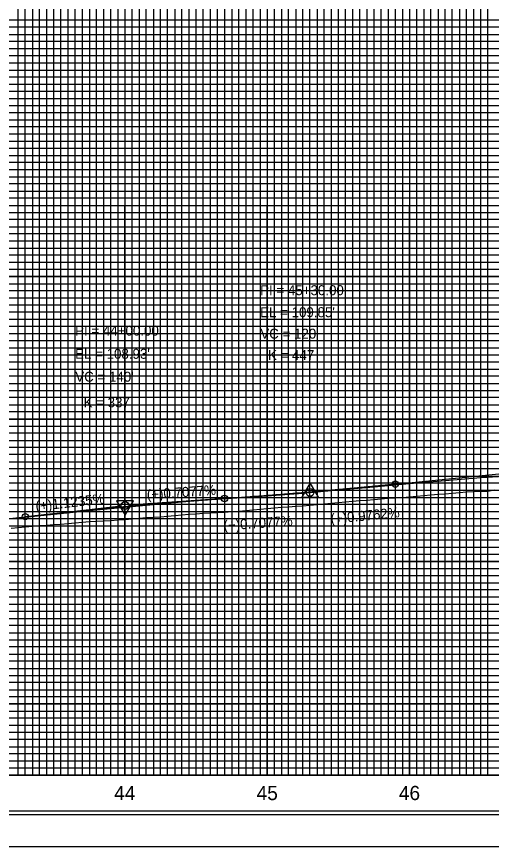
# Model space of a CAD drawing. Extents: x 2345490 to 2436403, y 465165 to 573888.
# Drawn here: x 2385091 to 2385424, y 515088 to 515670 of the extents above; entities that cross this region are included whole.
import ezdxf

# ---------------------------------------------------------------- set-up
doc = ezdxf.new("R2010")
doc.units = 0
for name, color, linetype in [('Old_Level_1', 7, 'Continuous'), ('Old_Level_18', 7, 'Continuous'), ('Old_Level_2', 7, 'Continuous'), ('Old_Level_41', 7, 'Continuous'), ('Old_Level_42', 7, 'Continuous'), ('Old_Level_43', 7, 'Continuous'), ('Old_Level_50', 7, 'Continuous'), ('Old_Level_51', 7, 'Continuous'), ('Old_Level_57', 7, 'Continuous'), ('Old_Level_61', 7, 'Continuous'), ('Old_Level_62', 7, 'Continuous'), ('Old_Level_63', 7, 'Continuous')]:
    doc.layers.add(name, color=color, linetype=linetype)

msp = doc.modelspace()

# ---------------------------------------------------------------- linework, layer by layer
at = {"layer": 'Old_Level_1'}
for points in [[(2385266.799, 515324.72275), (2385271.799, 515325.179), (2385276.799, 515325.58875), (2385281.799, 515325.93025), (2385286.799, 515326.27175), (2385291.799, 515326.662), (2385296.799, 515327.1245), (2385301.799, 515327.5825), (2385306.799, 515328.0385), (2385311.799, 515328.4945), (2385316.799, 515328.90475), (2385321.799, 515329.3655), (2385326.799, 515329.828), (2385331.799, 515330.2905), (2385336.799, 515330.61575), (2385341.799, 515330.98925), (2385346.799, 515331.45175), (2385351.799, 515331.91425), (2385356.799, 515332.30325), (2385361.799, 515332.5325), (2385366.799, 515332.9715), (2385371.799, 515333.41175), (2385376.799, 515333.852), (2385381.799, 515334.2775), (2385386.799, 515334.6985), (2385391.799, 515335.11925), (2385396.799, 515335.54025), (2385401.799, 515335.961), (2385406.799, 515336.382), (2385411.799, 515336.64275), (2385416.799, 515336.78), (2385421.799, 515336.9175), (2385426.799, 515337.8635)], [(2385086.799, 515310.91325), (2385091.799, 515311.27425), (2385096.799, 515311.77975), (2385101.799, 515312.285), (2385106.799, 515312.7905), (2385111.799, 515313.12575), (2385116.799, 515313.418), (2385121.799, 515313.7105), (2385126.799, 515314.17125), (2385131.799, 515314.6765), (2385136.799, 515315.182), (2385141.799, 515315.51675), (2385146.799, 515315.80925), (2385151.799, 515316.1015), (2385156.799, 515316.3905), (2385161.799, 515316.6785), (2385166.799, 515317.07925), (2385171.799, 515317.5565), (2385176.799, 515318.03375), (2385181.799, 515318.368), (2385186.799, 515318.65625), (2385191.799, 515318.9445), (2385196.799, 515319.3745), (2385201.799, 515319.85175), (2385206.799, 515320.32875), (2385211.799, 515320.70325), (2385216.799, 515321.045), (2385221.799, 515321.3505), (2385226.799, 515321.639), (2385231.799, 515321.9275), (2385236.799, 515322.25175), (2385241.799, 515322.5935), (2385246.799, 515322.93525), (2385251.799, 515323.35425), (2385256.799, 515323.8105), (2385261.799, 515324.2665), (2385266.799, 515324.72275)]]:
    msp.add_lwpolyline(points, dxfattribs=at)
at = {"layer": 'Old_Level_18'}
msp.add_lwpolyline([(2386016.79875, 516162.5265), (2384516.79875, 516162.5265), (2384516.79875, 515112.5265), (2386016.79875, 515112.5265)], close=True, dxfattribs=at)
at = {"layer": 'Old_Level_2'}
for p, q in [((2385356.799, 515341.88375), (2385431.799, 515349.20525)), ((2385356.799, 515341.88375), (2385299.536, 515336.29375)), ((2385236.799, 515331.7805), (2385294.056, 515335.8325)), ((2385096.799, 515318.962), (2385164.06625, 515326.5195)), ((2385236.799, 515331.7805), (2385169.54225, 515327.02075)), ((2385076.799, 515316.71475), (2385096.799, 515318.962))]:
    msp.add_line(p, q, dxfattribs=at)
for points in [[(2385290.99325, 515332.5755), (2385302.73575, 515332.5755), (2385296.86475, 515342.70125)], [(2385172.72475, 515330.111), (2385160.98225, 515330.0965), (2385166.86575, 515319.97825)]]:
    msp.add_lwpolyline(points, close=True, dxfattribs=at)
for centre, radius in [((2385356.799, 515341.88375), 2.25), ((2385296.799, 515336.0265), 2.75), ((2385236.799, 515331.7805), 2.25), ((2385166.799, 515326.8265), 2.75), ((2385166.799, 515326.8265), 2.75), ((2385096.799, 515318.962), 2.25)]:
    msp.add_circle(centre, radius, dxfattribs=at)
for points in [[(2385236.799, 515331.7805), (2385239.199, 515331.951), (2385241.599, 515332.12275), (2385243.999, 515332.29575), (2385246.399, 515332.47025), (2385248.799, 515332.64575), (2385251.199, 515332.82275), (2385253.599, 515333.001), (2385255.999, 515333.1805), (2385258.399, 515333.36125), (2385260.799, 515333.54325), (2385263.199, 515333.72675), (2385265.599, 515333.9115), (2385267.999, 515334.09725), (2385270.399, 515334.2845), (2385272.799, 515334.47325), (2385275.199, 515334.663), (2385277.599, 515334.854), (2385279.999, 515335.0465), (2385282.399, 515335.24025), (2385284.799, 515335.43525), (2385287.199, 515335.6315), (2385289.599, 515335.829), (2385291.999, 515336.02775), (2385294.399, 515336.228), (2385296.799, 515336.42925), (2385299.199, 515336.632), (2385301.599, 515336.836), (2385303.999, 515337.04125), (2385306.399, 515337.248), (2385308.799, 515337.45575), (2385311.199, 515337.665), (2385313.599, 515337.8755), (2385315.999, 515338.08725), (2385318.399, 515338.30025), (2385320.799, 515338.5145), (2385323.199, 515338.73), (2385325.599, 515338.947), (2385327.999, 515339.16525), (2385330.399, 515339.3845), (2385332.799, 515339.60525), (2385335.199, 515339.8275), (2385337.599, 515340.05075), (2385339.999, 515340.27525), (2385342.399, 515340.50125), (2385344.799, 515340.7285), (2385347.199, 515340.957), (2385349.599, 515341.18675), (2385351.999, 515341.41775), (2385354.399, 515341.65025), (2385356.799, 515341.88375)], [(2385096.799, 515318.962), (2385099.599, 515319.27525), (2385102.399, 515319.5865), (2385105.199, 515319.89525), (2385107.999, 515320.20175), (2385110.799, 515320.50575), (2385113.599, 515320.8075), (2385116.399, 515321.107), (2385119.199, 515321.404), (2385121.999, 515321.699), (2385124.799, 515321.99125), (2385127.599, 515322.2815), (2385130.399, 515322.56925), (2385133.199, 515322.85475), (2385135.999, 515323.138), (2385138.799, 515323.41875), (2385141.599, 515323.69725), (2385144.399, 515323.9735), (2385147.199, 515324.24725), (2385149.999, 515324.51875), (2385152.799, 515324.788), (2385155.599, 515325.05475), (2385158.399, 515325.31925), (2385161.199, 515325.5815), (2385163.999, 515325.84125), (2385166.799, 515326.099), (2385169.599, 515326.354), (2385172.399, 515326.607), (2385175.199, 515326.8575), (2385177.999, 515327.10575), (2385180.799, 515327.35175), (2385183.599, 515327.59525), (2385186.399, 515327.8365), (2385189.199, 515328.07525), (2385191.999, 515328.312), (2385194.799, 515328.54625), (2385197.599, 515328.778), (2385200.399, 515329.00775), (2385203.199, 515329.235), (2385205.999, 515329.46), (2385208.799, 515329.6825), (2385211.599, 515329.90275), (2385214.399, 515330.12075), (2385217.199, 515330.33625), (2385219.999, 515330.54975), (2385222.799, 515330.7605), (2385225.599, 515330.96925), (2385228.399, 515331.1755), (2385231.199, 515331.3795), (2385233.999, 515331.58125), (2385236.799, 515331.7805)]]:
    msp.add_spline(points, degree=3, dxfattribs=at)
at = {"layer": 'Old_Level_41'}
msp.add_line((2386016.79875, 515137.5265), (2384516.79875, 515137.5265), dxfattribs=at)
for points in [[(2385041.79875, 515137.5265), (2385091.79875, 515137.5265), (2385091.79875, 516162.5265)], [(2385066.79875, 515137.5265), (2385116.79875, 515137.5265), (2385116.79875, 516162.5265)], [(2385141.79875, 516162.5265), (2385141.79875, 515137.5265), (2385191.79875, 515137.5265), (2385191.79875, 516162.5265)], [(2385166.79875, 516162.5265), (2385166.79875, 515137.5265), (2385216.79875, 515137.5265), (2385216.79875, 516162.5265)], [(2385241.79875, 516162.5265), (2385241.79875, 515137.5265), (2385291.79875, 515137.5265), (2385291.79875, 516162.5265)], [(2385266.79875, 516162.5265), (2385266.79875, 515137.5265), (2385316.79875, 515137.5265), (2385316.79875, 516162.5265)], [(2385341.79875, 516162.5265), (2385341.79875, 515137.5265), (2385391.79875, 515137.5265), (2385391.79875, 516162.5265)], [(2385366.79875, 516162.5265), (2385366.79875, 515137.5265), (2385416.79875, 515137.5265), (2385416.79875, 516162.5265)], [(2386016.79875, 515662.5265), (2384516.79875, 515662.5265), (2384516.79875, 515612.5265), (2386016.79875, 515612.5265)], [(2386016.79875, 515562.5265), (2384516.79875, 515562.5265), (2384516.79875, 515512.5265), (2386016.79875, 515512.5265)], [(2386016.79875, 515487.5265), (2384516.79875, 515487.5265), (2384516.79875, 515537.5265), (2386016.79875, 515537.5265)], [(2386016.79875, 515462.5265), (2384516.79875, 515462.5265), (2384516.79875, 515412.5265), (2386016.79875, 515412.5265)], [(2386016.79875, 515387.5265), (2384516.79875, 515387.5265), (2384516.79875, 515437.5265), (2386016.79875, 515437.5265)], [(2386016.79875, 515362.5265), (2384516.79875, 515362.5265), (2384516.79875, 515312.5265), (2386016.79875, 515312.5265)], [(2386016.79875, 515262.5265), (2384516.79875, 515262.5265), (2384516.79875, 515212.5265), (2386016.79875, 515212.5265)], [(2386016.79875, 515187.5265), (2384516.79875, 515187.5265), (2384516.79875, 515237.5265), (2386016.79875, 515237.5265)], [(2386016.79875, 515162.5265), (2384516.79875, 515162.5265)]]:
    msp.add_lwpolyline(points, dxfattribs=at)
at = {"layer": 'Old_Level_42'}
for points in [[(2386016.79875, 515587.5265), (2384516.79875, 515587.5265), (2384516.79875, 515637.5265), (2386016.79875, 515637.5265)], [(2386016.79875, 515287.5265), (2384516.79875, 515287.5265), (2384516.79875, 515337.5265), (2386016.79875, 515337.5265)]]:
    msp.add_lwpolyline(points, dxfattribs=at)
at = {"layer": 'Old_Level_43'}
for points in [[(2385096.79875, 515137.5265), (2385096.79875, 516162.5265)], [(2385101.79875, 516162.5265), (2385101.79875, 515137.5265), (2385106.79875, 515137.5265), (2385106.79875, 516162.5265)], [(2385111.79875, 516162.5265), (2385111.79875, 515137.5265), (2385121.79875, 515137.5265), (2385121.79875, 516162.5265)], [(2385126.79875, 516162.5265), (2385126.79875, 515137.5265), (2385126.79875, 515137.5265), (2385131.79875, 515137.5265), (2385131.79875, 516162.5265)], [(2385136.79875, 516162.5265), (2385136.79875, 515137.5265), (2385146.79875, 515137.5265), (2385146.79875, 516162.5265)], [(2385151.79875, 516162.5265), (2385151.79875, 515137.5265), (2385156.79875, 515137.5265), (2385156.79875, 516162.5265)], [(2385161.79875, 516162.5265), (2385161.79875, 515137.5265), (2385171.79875, 515137.5265), (2385171.79875, 516162.5265)], [(2385176.79875, 516162.5265), (2385176.79875, 515137.5265), (2385181.79875, 515137.5265), (2385181.79875, 516162.5265)], [(2385186.79875, 516162.5265), (2385186.79875, 515137.5265), (2385196.79875, 515137.5265), (2385196.79875, 516162.5265)], [(2385201.79875, 516162.5265), (2385201.79875, 515137.5265), (2385206.79875, 515137.5265), (2385206.79875, 516162.5265)], [(2385211.79875, 516162.5265), (2385211.79875, 515137.5265), (2385221.79875, 515137.5265), (2385221.79875, 516162.5265)], [(2385226.79875, 516162.5265), (2385226.79875, 515137.5265), (2385231.79875, 515137.5265), (2385231.79875, 516162.5265)], [(2385236.79875, 516162.5265), (2385236.79875, 515137.5265), (2385246.79875, 515137.5265), (2385246.79875, 516162.5265)], [(2385251.79875, 516162.5265), (2385251.79875, 515137.5265), (2385256.79875, 515137.5265), (2385256.79875, 516162.5265)], [(2385261.79875, 516162.5265), (2385261.79875, 515137.5265), (2385271.79875, 515137.5265), (2385271.79875, 516162.5265)], [(2385276.79875, 516162.5265), (2385276.79875, 515137.5265)], [(2385276.79875, 515137.5265), (2385281.79875, 515137.5265), (2385281.79875, 516161.9265)], [(2385286.79875, 516161.9265), (2385286.79875, 515137.5265), (2385296.79875, 515137.5265), (2385296.79875, 516162.5265)], [(2385301.79875, 516162.5265), (2385301.79875, 515137.5265), (2385306.79875, 515137.5265), (2385306.79875, 516162.5265)], [(2385311.79875, 516162.5265), (2385311.79875, 515137.5265), (2385321.79875, 515137.5265), (2385321.79875, 516162.5265)], [(2385326.79875, 516162.5265), (2385326.79875, 515137.5265), (2385331.79875, 515137.5265), (2385331.79875, 516162.5265)], [(2385336.79875, 516162.5265), (2385336.79875, 515137.5265), (2385346.79875, 515137.5265), (2385346.79875, 516162.5265)], [(2385351.79875, 516162.5265), (2385351.79875, 515137.5265), (2385356.79875, 515137.5265), (2385356.79875, 516162.5265)], [(2385361.79875, 516162.5265), (2385361.79875, 515137.5265), (2385371.79875, 515137.5265), (2385371.79875, 516162.5265)], [(2385376.79875, 516162.5265), (2385376.79875, 515137.5265), (2385381.79875, 515137.5265), (2385381.79875, 516162.5265)], [(2385386.79875, 516162.5265), (2385386.79875, 515137.5265), (2385396.79875, 515137.5265), (2385396.79875, 516162.5265)], [(2385401.79875, 516162.5265), (2385401.79875, 515137.5265), (2385406.79875, 515137.5265), (2385406.79875, 516162.5265)], [(2385411.79875, 516162.5265), (2385411.79875, 515137.5265), (2385421.79875, 515137.5265), (2385421.79875, 516162.5265)], [(2385966.79875, 515667.5265), (2384566.79875, 515667.5265), (2384566.79875, 515657.5265), (2385966.79875, 515657.5265)], [(2385966.79875, 515652.5265), (2384566.79875, 515652.5265), (2384566.79875, 515647.5265), (2385966.79875, 515647.5265)], [(2385966.79875, 515642.5265), (2384566.79875, 515642.5265)], [(2384566.79875, 515632.5265), (2385966.79875, 515632.5265)], [(2385966.79875, 515627.5265), (2384566.79875, 515627.5265), (2384566.79875, 515622.5265), (2385966.79875, 515622.5265)], [(2385966.79875, 515617.5265), (2384566.79875, 515617.5265), (2384566.79875, 515607.5265), (2385966.79875, 515607.5265)], [(2385966.79875, 515602.5265), (2384566.79875, 515602.5265), (2384566.79875, 515597.5265), (2385966.79875, 515597.5265)], [(2385966.79875, 515592.5265), (2384566.79875, 515592.5265), (2384566.79875, 515582.5265), (2385966.79875, 515582.5265)], [(2385966.79875, 515577.5265), (2384566.79875, 515577.5265), (2384566.79875, 515572.5265), (2385966.79875, 515572.5265)], [(2385966.79875, 515567.5265), (2384566.79875, 515567.5265), (2384566.79875, 515557.5265), (2385966.79875, 515557.5265)], [(2385966.79875, 515552.5265), (2384566.79875, 515552.5265), (2384566.79875, 515547.5265), (2385966.79875, 515547.5265)], [(2385966.79875, 515542.5265), (2384566.79875, 515542.5265), (2384566.79875, 515532.5265), (2385966.79875, 515532.5265)], [(2385966.79875, 515527.5265), (2384566.79875, 515527.5265), (2384566.79875, 515522.5265), (2385966.79875, 515522.5265)], [(2385966.79875, 515517.5265), (2384566.79875, 515517.5265), (2384566.79875, 515507.5265), (2385966.79875, 515507.5265)], [(2385966.79875, 515502.5265), (2384566.79875, 515502.5265), (2384566.79875, 515497.5265), (2385966.79875, 515497.5265)], [(2385966.79875, 515492.5265), (2384566.79875, 515492.5265), (2384566.79875, 515482.5265), (2385966.79875, 515482.5265)], [(2385966.79875, 515477.5265), (2384566.79875, 515477.5265), (2384566.79875, 515472.5265), (2385966.79875, 515472.5265)], [(2385966.79875, 515467.5265), (2384566.79875, 515467.5265), (2384566.79875, 515457.5265), (2385966.79875, 515457.5265)], [(2385966.79875, 515452.5265), (2384566.79875, 515452.5265), (2384566.79875, 515447.5265), (2385966.79875, 515447.5265)], [(2385966.79875, 515442.5265), (2384566.79875, 515442.5265), (2384566.79875, 515432.5265), (2385966.79875, 515432.5265)], [(2385966.79875, 515427.5265), (2384566.79875, 515427.5265), (2384566.79875, 515422.5265), (2385966.79875, 515422.5265)], [(2385966.79875, 515417.5265), (2384566.79875, 515417.5265), (2384566.79875, 515407.5265), (2385966.79875, 515407.5265)], [(2385966.79875, 515402.5265), (2384566.79875, 515402.5265), (2384566.79875, 515397.5265), (2385966.79875, 515397.5265)], [(2385966.79875, 515392.5265), (2384566.79875, 515392.5265), (2384566.79875, 515382.5265), (2385966.79875, 515382.5265)], [(2385966.79875, 515377.5265), (2384566.79875, 515377.5265), (2384566.79875, 515372.5265), (2385966.79875, 515372.5265)], [(2385966.79875, 515367.5265), (2384566.79875, 515367.5265), (2384566.79875, 515357.5265), (2385966.79875, 515357.5265)], [(2385966.79875, 515352.5265), (2384566.79875, 515352.5265), (2384566.79875, 515347.5265), (2385966.79875, 515347.5265)], [(2385966.79875, 515342.5265), (2384566.79875, 515342.5265)], [(2384566.79875, 515332.5265), (2385966.79875, 515332.5265)], [(2385966.79875, 515327.5265), (2384566.79875, 515327.5265), (2384566.79875, 515322.5265), (2385966.79875, 515322.5265)], [(2385966.79875, 515317.5265), (2384566.79875, 515317.5265)], [(2384566.79875, 515307.5265), (2385966.79875, 515307.5265)], [(2385966.79875, 515302.5265), (2384566.79875, 515302.5265), (2384566.79875, 515297.5265), (2385966.79875, 515297.5265)], [(2385966.79875, 515292.5265), (2384566.79875, 515292.5265), (2384566.79875, 515282.5265), (2385966.79875, 515282.5265)], [(2385966.79875, 515277.5265), (2384566.79875, 515277.5265), (2384566.79875, 515272.5265), (2385966.79875, 515272.5265)], [(2385966.79875, 515267.5265), (2384566.79875, 515267.5265), (2384566.79875, 515257.5265), (2385966.79875, 515257.5265)], [(2385966.79875, 515252.5265), (2384566.79875, 515252.5265), (2384566.79875, 515247.5265), (2385966.79875, 515247.5265)], [(2385966.79875, 515242.5265), (2384566.79875, 515242.5265), (2384566.79875, 515232.5265), (2385966.79875, 515232.5265)], [(2385966.79875, 515227.5265), (2384566.79875, 515227.5265), (2384566.79875, 515222.5265), (2385966.79875, 515222.5265)], [(2385966.79875, 515217.5265), (2384566.79875, 515217.5265), (2384566.79875, 515207.5265), (2385966.79875, 515207.5265)], [(2385966.79875, 515202.5265), (2384566.79875, 515202.5265), (2384566.79875, 515197.5265), (2385966.79875, 515197.5265)], [(2385966.79875, 515192.5265), (2384566.79875, 515192.5265), (2384566.79875, 515182.5265), (2385966.79875, 515182.5265)], [(2385966.79875, 515177.5265), (2384566.79875, 515177.5265), (2384566.79875, 515172.5265), (2385966.79875, 515172.5265)], [(2385966.79875, 515167.5265), (2384566.79875, 515167.5265), (2384566.79875, 515157.5265), (2385966.79875, 515157.5265)], [(2385966.79875, 515152.5265), (2384566.79875, 515152.5265), (2384566.79875, 515147.5265), (2385966.79875, 515147.5265)], [(2385966.79875, 515142.5265), (2384566.79875, 515142.5265)]]:
    msp.add_lwpolyline(points, dxfattribs=at)
at = {"layer": 'Old_Level_50'}
msp.add_lwpolyline([(2386029.29875, 516165.0765), (2384362.79875, 516165.0765), (2384362.79875, 515109.9765), (2386029.29875, 515109.9765)], close=True, dxfattribs=at)
at = {"layer": 'Old_Level_51'}
msp.add_lwpolyline([(2386033.79875, 516187.5265), (2384349.79875, 516187.5265), (2384349.79875, 515087.5265), (2386033.79875, 515087.5265)], close=True, dxfattribs=at)
at = {"layer": 'Old_Level_57'}
for p, q in [((2381716.79925, 515537.52675), (2386366.79875, 515537.52675)), ((2385166.79875, 515137.52675), (2385166.79875, 515537.52675)), ((2385166.79875, 515137.62675), (2385166.79875, 515537.52675)), ((2385266.79875, 515137.52675), (2385266.79875, 515537.52675)), ((2385266.79875, 515137.62675), (2385266.79875, 515537.52675)), ((2385366.79875, 515137.52675), (2385366.79875, 515537.52675)), ((2385366.79875, 515137.62675), (2385366.79875, 515537.52675)), ((2381716.79925, 515487.52675), (2386366.79875, 515487.52675)), ((2381716.79925, 515437.52675), (2386366.79875, 515437.52675)), ((2381716.79925, 515387.52675), (2386366.79875, 515387.52675)), ((2381716.79925, 515337.52675), (2386366.79875, 515337.52675)), ((2381716.79925, 515287.52675), (2386366.79875, 515287.52675)), ((2381716.79925, 515237.52675), (2386366.79875, 515237.52675)), ((2381716.799, 515187.52675), (2386366.79875, 515187.52675)), ((2381716.79925, 515137.52675), (2386366.79875, 515137.52675))]:
    msp.add_line(p, q, dxfattribs=at)
at = {"layer": 'Old_Level_61'}
msp.add_lwpolyline([(2385066.799, 515315.50575), (2385091.799, 515318.182), (2385116.799, 515320.70925), (2385141.799, 515323.23575), (2385166.799, 515325.687), (2385191.799, 515328.08125), (2385216.799, 515330.2955), (2385241.799, 515331.987), (2385266.799, 515333.68625), (2385291.799, 515335.4015), (2385316.799, 515337.717), (2385341.799, 515340.03625), (2385366.799, 515342.3545), (2385391.799, 515344.47275), (2385416.799, 515346.579), (2385441.799, 515347.9905), (2385466.799, 515350.68375)], dxfattribs=at)
at = {"layer": 'Old_Level_63'}
msp.add_line((2381766.79875, 515137.5265), (2386228.05125, 515137.5265), dxfattribs=at)

# ---------------------------------------------------------------- texts
at = {"layer": 'Old_Level_2'}
for s, height, p in [('PI = 45+30.00', 7.0000005, (2385261.79925, 515474.45875)), ("EL = 109.85'", 7.0000005, (2385261.799, 515459.0265)), ('PI = 44+00.00', 7.0000005, (2385131.799, 515446.08925)), ("VC = 120'", 7.000001, (2385261.927, 515443.95025)), ("EL = 108.93'", 7.0000005, (2385131.799, 515429.8265)), ('K = 447', 7.000001, (2385267.324, 515428.8815)), ("VC = 140'", 7.000001, (2385131.927, 515413.73125)), ('K = 337', 7.000001, (2385137.739, 515395.7555))]:
    msp.add_text(s, height=height, dxfattribs=at).set_placement(p)
for s, rotation, p in [('(+)0.7077%', 4.04803056, (2385182.40825, 515330.939)), ('(+)1.1235%', 6.41046667, (2385104.37125, 515322.8315)), ('(+)0.9762%', 5.57549444, (2385311.61, 515313.91175)), ('(+)0.7077%', 4.04803056, (2385236.325, 515309.274))]:
    msp.add_text(s, height=7.000001, rotation=rotation, dxfattribs=at).set_placement(p)
at = {"layer": 'Old_Level_62'}
for s, p in [('44', (2385159.2505, 515120.0265)), ('45', (2385259.343, 515120.0265)), ('46', (2385359.284, 515120.0265))]:
    msp.add_text(s, height=10.000001, dxfattribs=at).set_placement(p)

doc.saveas('drawing.dxf')
